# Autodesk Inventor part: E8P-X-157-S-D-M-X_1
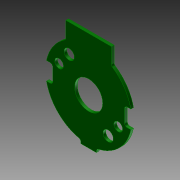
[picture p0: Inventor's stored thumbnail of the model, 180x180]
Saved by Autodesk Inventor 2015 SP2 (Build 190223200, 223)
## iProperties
Created: 2012-07
Part Number: E8P-X-157-S-D-M-X_1
Material: Allgemein
Document SubType Name: Modeling
Designer: rYan
Density: 1 g/cm^3
Mass: 0.369495 g
Surface Area: 10.5695 cm^2
Volume: 0.369495 cm^3
Appearance: Vorgabe
Author: rYan
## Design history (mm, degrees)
node "E8P-X-157-S-D-M-X_11"
node "E8P-X-157-S-D-M-X_1"
node "Basis1"
